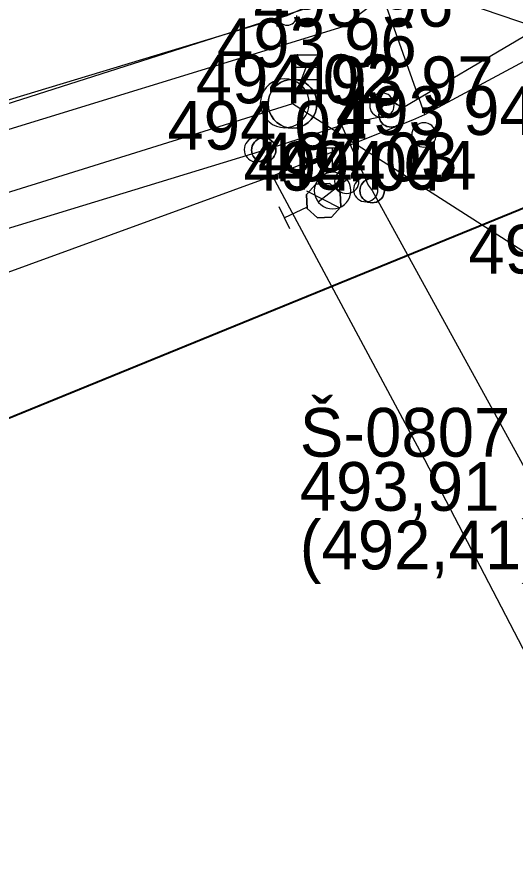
# Model space of a CAD drawing. Extents: x -695326 to -694942, y -1122979 to -1122738.
# Drawn here: x -695088.22 to -695078.02, y -1122949.89 to -1122932.52 of the extents above; entities that cross this region are included whole.
import ezdxf

# ---------------------------------------------------------------- set-up
doc = ezdxf.new("R2010")
doc.units = 0
for name, color, linetype in [('Level 26', 7, 'Continuous'), ('Level 29', 7, 'Continuous'), ('Level 30', 7, 'Continuous'), ('Level 31', 7, 'Continuous'), ('Level 35', 7, 'Continuous'), ('Level 36', 7, 'Continuous'), ('Level 38', 7, 'Continuous'), ('Level 42', 7, 'Continuous'), ('Level 44', 7, 'Continuous'), ('Level 48', 7, 'Continuous'), ('Level 51', 7, 'Continuous'), ('Level 53', 7, 'Continuous'), ('Rozhraní ploch', 7, 'Continuous')]:
    doc.layers.add(name, color=color, linetype=linetype)

msp = doc.modelspace()

# ---------------------------------------------------------------- linework, layer by layer
at = {"layer": 'Level 26'}
msp.add_lwpolyline([(-695082.89, -1122932.49), (-695082.887, -1122932.525), (-695082.878, -1122932.558), (-695082.863, -1122932.59), (-695082.843, -1122932.619), (-695082.819, -1122932.643), (-695082.79, -1122932.663), (-695082.758, -1122932.678), (-695082.725, -1122932.687), (-695082.69, -1122932.69), (-695082.655, -1122932.687), (-695082.622, -1122932.678), (-695082.59, -1122932.663), (-695082.561, -1122932.643), (-695082.537, -1122932.619), (-695082.517, -1122932.59), (-695082.502, -1122932.558), (-695082.493, -1122932.525), (-695082.49, -1122932.49)], dxfattribs=at)
at = {"layer": 'Level 29'}
for p, q in [((-695080.75, -1122934.33), (-695080.75, -1122934.33)), ((-695083.32, -1122935.24), (-695083.32, -1122935.24)), ((-695081.47, -1122935.89), (-695081.47, -1122935.89)), ((-695081.76, -1122936.08), (-695081.76, -1122936.08)), ((-695081.08, -1122936.06), (-695081.08, -1122936.06))]:
    msp.add_line(p, q, dxfattribs=at)
for points in [[(-695080.5, -1122934.33), (-695080.504, -1122934.287), (-695080.515, -1122934.244), (-695080.533, -1122934.205), (-695080.558, -1122934.169), (-695080.589, -1122934.138), (-695080.625, -1122934.113), (-695080.664, -1122934.095), (-695080.707, -1122934.084), (-695080.75, -1122934.08), (-695080.793, -1122934.084), (-695080.836, -1122934.095), (-695080.875, -1122934.113), (-695080.911, -1122934.138), (-695080.942, -1122934.169), (-695080.967, -1122934.205), (-695080.985, -1122934.244), (-695080.996, -1122934.287), (-695081, -1122934.33), (-695080.996, -1122934.373), (-695080.985, -1122934.416), (-695080.967, -1122934.455), (-695080.942, -1122934.491), (-695080.911, -1122934.522), (-695080.875, -1122934.547), (-695080.836, -1122934.565), (-695080.793, -1122934.576), (-695080.75, -1122934.58), (-695080.707, -1122934.576), (-695080.664, -1122934.565), (-695080.625, -1122934.547), (-695080.589, -1122934.522), (-695080.558, -1122934.491), (-695080.533, -1122934.455), (-695080.515, -1122934.416), (-695080.504, -1122934.373), (-695080.5, -1122934.33)], [(-695083.07, -1122935.24), (-695083.074, -1122935.197), (-695083.085, -1122935.154), (-695083.103, -1122935.115), (-695083.128, -1122935.079), (-695083.159, -1122935.048), (-695083.195, -1122935.023), (-695083.234, -1122935.005), (-695083.277, -1122934.994), (-695083.32, -1122934.99), (-695083.363, -1122934.994), (-695083.406, -1122935.005), (-695083.445, -1122935.023), (-695083.481, -1122935.048), (-695083.512, -1122935.079), (-695083.537, -1122935.115), (-695083.555, -1122935.154), (-695083.566, -1122935.197), (-695083.57, -1122935.24), (-695083.566, -1122935.283), (-695083.555, -1122935.326), (-695083.537, -1122935.365), (-695083.512, -1122935.401), (-695083.481, -1122935.432), (-695083.445, -1122935.457), (-695083.406, -1122935.475), (-695083.363, -1122935.486), (-695083.32, -1122935.49), (-695083.277, -1122935.486), (-695083.234, -1122935.475), (-695083.195, -1122935.457), (-695083.159, -1122935.432), (-695083.128, -1122935.401), (-695083.103, -1122935.365), (-695083.085, -1122935.326), (-695083.074, -1122935.283), (-695083.07, -1122935.24)], [(-695082.01, -1122935.205), (-695081.51, -1122935.205)], [(-695081.76, -1122935.705), (-695081.76, -1122935.205)], [(-695081.22, -1122935.89), (-695081.224, -1122935.847), (-695081.235, -1122935.804), (-695081.253, -1122935.765), (-695081.278, -1122935.729), (-695081.309, -1122935.698), (-695081.345, -1122935.673), (-695081.384, -1122935.655), (-695081.427, -1122935.644), (-695081.47, -1122935.64), (-695081.513, -1122935.644), (-695081.556, -1122935.655), (-695081.595, -1122935.673), (-695081.631, -1122935.698), (-695081.662, -1122935.729), (-695081.687, -1122935.765), (-695081.705, -1122935.804), (-695081.716, -1122935.847), (-695081.72, -1122935.89), (-695081.716, -1122935.933), (-695081.705, -1122935.976), (-695081.687, -1122936.015), (-695081.662, -1122936.051), (-695081.631, -1122936.082), (-695081.595, -1122936.107), (-695081.556, -1122936.125), (-695081.513, -1122936.136), (-695081.47, -1122936.14), (-695081.427, -1122936.136), (-695081.384, -1122936.125), (-695081.345, -1122936.107), (-695081.309, -1122936.082), (-695081.278, -1122936.051), (-695081.253, -1122936.015), (-695081.235, -1122935.976), (-695081.224, -1122935.933), (-695081.22, -1122935.89)], [(-695081.385, -1122936.08), (-695081.391, -1122936.015), (-695081.408, -1122935.952), (-695081.435, -1122935.892), (-695081.473, -1122935.839), (-695081.519, -1122935.793), (-695081.572, -1122935.755), (-695081.632, -1122935.728), (-695081.695, -1122935.711), (-695081.76, -1122935.705), (-695081.825, -1122935.711), (-695081.888, -1122935.728), (-695081.947, -1122935.755), (-695082.001, -1122935.793), (-695082.047, -1122935.839), (-695082.085, -1122935.892), (-695082.112, -1122935.952), (-695082.129, -1122936.015), (-695082.135, -1122936.08), (-695082.129, -1122936.145), (-695082.112, -1122936.208), (-695082.085, -1122936.267), (-695082.047, -1122936.321), (-695082.001, -1122936.367), (-695081.947, -1122936.405), (-695081.888, -1122936.432), (-695081.825, -1122936.449), (-695081.76, -1122936.455), (-695081.695, -1122936.449), (-695081.632, -1122936.432), (-695081.572, -1122936.405), (-695081.519, -1122936.367), (-695081.473, -1122936.321), (-695081.435, -1122936.267), (-695081.408, -1122936.208), (-695081.391, -1122936.145), (-695081.385, -1122936.08)], [(-695080.83, -1122936.06), (-695080.834, -1122936.017), (-695080.845, -1122935.974), (-695080.863, -1122935.935), (-695080.888, -1122935.899), (-695080.919, -1122935.868), (-695080.955, -1122935.843), (-695080.994, -1122935.825), (-695081.037, -1122935.814), (-695081.08, -1122935.81), (-695081.123, -1122935.814), (-695081.166, -1122935.825), (-695081.205, -1122935.843), (-695081.241, -1122935.868), (-695081.272, -1122935.899), (-695081.297, -1122935.935), (-695081.315, -1122935.974), (-695081.326, -1122936.017), (-695081.33, -1122936.06), (-695081.326, -1122936.103), (-695081.315, -1122936.146), (-695081.297, -1122936.185), (-695081.272, -1122936.221), (-695081.241, -1122936.252), (-695081.205, -1122936.277), (-695081.166, -1122936.295), (-695081.123, -1122936.306), (-695081.08, -1122936.31), (-695081.037, -1122936.306), (-695080.994, -1122936.295), (-695080.955, -1122936.277), (-695080.919, -1122936.252), (-695080.888, -1122936.221), (-695080.863, -1122936.185), (-695080.845, -1122936.146), (-695080.834, -1122936.103), (-695080.83, -1122936.06)], [(-695082.054, -1122936.311), (-695081.464, -1122935.848)]]:
    msp.add_lwpolyline(points, dxfattribs=at)
at = {"layer": 'Level 30'}
for p, q in [((-695082.3, -1122933.55), (-695082.3, -1122933.55)), ((-695082.74, -1122934.29), (-695082.74, -1122934.29))]:
    msp.add_line(p, q, dxfattribs=at)
for points in [[(-695082.55, -1122933.801), (-695082.05, -1122933.801), (-695082.05, -1122933.3), (-695082.55, -1122933.3), (-695082.55, -1122933.801)], [(-695082.55, -1122933.55), (-695082.05, -1122933.55)], [(-695082.24, -1122934.29), (-695082.248, -1122934.203), (-695082.27, -1122934.119), (-695082.307, -1122934.04), (-695082.357, -1122933.969), (-695082.419, -1122933.907), (-695082.49, -1122933.857), (-695082.569, -1122933.82), (-695082.653, -1122933.798), (-695082.74, -1122933.79), (-695082.827, -1122933.798), (-695082.911, -1122933.82), (-695082.99, -1122933.857), (-695083.061, -1122933.907), (-695083.123, -1122933.969), (-695083.173, -1122934.04), (-695083.21, -1122934.119), (-695083.232, -1122934.203), (-695083.24, -1122934.29), (-695083.232, -1122934.377), (-695083.21, -1122934.461), (-695083.173, -1122934.54), (-695083.123, -1122934.611), (-695083.061, -1122934.673), (-695082.99, -1122934.723), (-695082.911, -1122934.76), (-695082.827, -1122934.782), (-695082.74, -1122934.79), (-695082.653, -1122934.782), (-695082.569, -1122934.76), (-695082.49, -1122934.723), (-695082.419, -1122934.673), (-695082.357, -1122934.611), (-695082.307, -1122934.54), (-695082.27, -1122934.461), (-695082.248, -1122934.377), (-695082.24, -1122934.29)]]:
    msp.add_lwpolyline(points, dxfattribs=at)
at = {"layer": 'Level 31'}
msp.add_line((-695079.89, -1122934.94), (-695079.89, -1122934.94), dxfattribs=at)
msp.add_lwpolyline([(-695079.64, -1122934.94), (-695079.644, -1122934.897), (-695079.655, -1122934.854), (-695079.673, -1122934.815), (-695079.698, -1122934.779), (-695079.729, -1122934.748), (-695079.765, -1122934.723), (-695079.804, -1122934.705), (-695079.847, -1122934.694), (-695079.89, -1122934.69), (-695079.933, -1122934.694), (-695079.976, -1122934.705), (-695080.015, -1122934.723), (-695080.051, -1122934.748), (-695080.082, -1122934.779), (-695080.107, -1122934.815), (-695080.125, -1122934.854), (-695080.136, -1122934.897), (-695080.14, -1122934.94), (-695080.136, -1122934.983), (-695080.125, -1122935.026), (-695080.107, -1122935.065), (-695080.082, -1122935.101), (-695080.051, -1122935.132), (-695080.015, -1122935.157), (-695079.976, -1122935.175), (-695079.933, -1122935.186), (-695079.89, -1122935.19), (-695079.847, -1122935.186), (-695079.804, -1122935.175), (-695079.765, -1122935.157), (-695079.729, -1122935.132), (-695079.698, -1122935.101), (-695079.673, -1122935.065), (-695079.655, -1122935.026), (-695079.644, -1122934.983), (-695079.64, -1122934.94)], dxfattribs=at)
at = {"layer": 'Level 35'}
msp.add_line((-695082.58, -1122934.3), (-695082.3, -1122933.55), dxfattribs=at)
for points in [[(-695122.183, -1122978.845), (-695130.45, -1122957.93), (-695095.39, -1122943.61), (-695072.77, -1122934.37), (-695099.42, -1122862.69)], [(-695131.247, -1122978.864), (-695132.65, -1122975.94), (-695157.61, -1122969.63), (-695140.47, -1122958.8), (-695136.63, -1122948.53), (-695119.01, -1122943.49), (-695100.79, -1122937.97), (-695082.69, -1122932.49), (-695067.48, -1122925.68), (-695054.28, -1122919.15), (-695039.04, -1122911.54), (-695024.78, -1122904.45), (-695010.56, -1122897.35), (-694996.02, -1122890.13), (-694983.12, -1122883.66), (-694965.65, -1122874.99), (-694952.69, -1122868.61), (-694948.627, -1122866.586)]]:
    msp.add_lwpolyline(points, dxfattribs=at)
at = {"layer": 'Level 36'}
for p, q in [((-695076.08, -1122931.88), (-695080.56, -1122934.53)), ((-695080.56, -1122934.53), (-695081.58, -1122934.74)), ((-695082.99, -1122935.78), (-695080.12, -1122934.63))]:
    msp.add_line(p, q, dxfattribs=at)
for points in [[(-695080.12, -1122934.63), (-695079.87, -1122934.52), (-695067.92, -1122928.09), (-695061.28, -1122924.38), (-695055.24, -1122920.99), (-695043.92, -1122915.38), (-695041.46, -1122911.18), (-695031.8, -1122906.42), (-695019.5, -1122900.12), (-695018.26, -1122899.49), (-695013.65, -1122897.25), (-695010.42, -1122895.62), (-694999.32, -1122890.29), (-694992.82, -1122887.05), (-694976.036, -1122879.197)], [(-695080.48, -1122922.5), (-695080.09, -1122922.37), (-695078.02, -1122927.55), (-695078.08, -1122929.81), (-695080.4, -1122930.84), (-695080.06, -1122931.88), (-695072.77, -1122934.37)], [(-695079.87, -1122934.52), (-695081.2, -1122930.76), (-695081.62, -1122930.91)], [(-695083.17, -1122935.25), (-695081.781, -1122934.805), (-695081.58, -1122934.74)], [(-695081.58, -1122934.74), (-695081.03, -1122935.97), (-695080.95, -1122936.08)], [(-695134.34, -1122973.03), (-695133.962, -1122972.86), (-695138.962, -1122954.566), (-695138.77, -1122954.48), (-695126.25, -1122948.73), (-695098.58, -1122939.97), (-695083.17, -1122935.25)], [(-695134.55, -1122961.53), (-695132.51, -1122957.25), (-695132.03, -1122956.26), (-695129.88, -1122955.26), (-695122.6, -1122951.79), (-695118.68, -1122949.8), (-695111.26, -1122946.33), (-695098.73, -1122941.53), (-695092.08, -1122939.09), (-695082.99, -1122935.78)], [(-695060.508, -1122978.714), (-695066.08, -1122968.01), (-695069.94, -1122960.81), (-695074.02, -1122952.86), (-695079.87, -1122941.6), (-695082.99, -1122935.78)], [(-695080.95, -1122936.08), (-695066.03, -1122963.27), (-695064.437, -1122966.165)]]:
    msp.add_lwpolyline(points, dxfattribs=at)
at = {"layer": 'Level 38'}
msp.add_line((-695077.1, -1122937.81), (-695082.58, -1122934.3), dxfattribs=at)
msp.add_lwpolyline([(-695082.58, -1122934.3), (-695132.114, -1122949.771), (-695137.17, -1122949.78)], dxfattribs=at)
at = {"layer": 'Level 42'}
msp.add_line((-695072.77, -1122934.36), (-695130.4, -1122957.89), dxfattribs=at)
at = {"layer": 'Level 44'}
for p, q in [((-695082.58, -1122934.3), (-695082.58, -1122934.3)), ((-695080.56, -1122934.53), (-695080.56, -1122934.53)), ((-695083.17, -1122935.25), (-695083.17, -1122935.25)), ((-695081.62, -1122936.12), (-695081.62, -1122936.12)), ((-695080.95, -1122936.08), (-695080.95, -1122936.08))]:
    msp.add_line(p, q, dxfattribs=at)
for points in [[(-695082.08, -1122934.3), (-695082.088, -1122934.213), (-695082.11, -1122934.129), (-695082.147, -1122934.05), (-695082.197, -1122933.979), (-695082.259, -1122933.917), (-695082.33, -1122933.867), (-695082.409, -1122933.83), (-695082.493, -1122933.808), (-695082.58, -1122933.8), (-695082.667, -1122933.808), (-695082.751, -1122933.83), (-695082.83, -1122933.867), (-695082.901, -1122933.917), (-695082.963, -1122933.979), (-695083.013, -1122934.05), (-695083.05, -1122934.129), (-695083.072, -1122934.213), (-695083.08, -1122934.3), (-695083.072, -1122934.387), (-695083.05, -1122934.471), (-695083.013, -1122934.55), (-695082.963, -1122934.621), (-695082.901, -1122934.683), (-695082.83, -1122934.733), (-695082.751, -1122934.77), (-695082.667, -1122934.792), (-695082.58, -1122934.8), (-695082.493, -1122934.792), (-695082.409, -1122934.77), (-695082.33, -1122934.733), (-695082.259, -1122934.683), (-695082.197, -1122934.621), (-695082.147, -1122934.55), (-695082.11, -1122934.471), (-695082.088, -1122934.387), (-695082.08, -1122934.3)], [(-695080.31, -1122934.53), (-695080.314, -1122934.487), (-695080.325, -1122934.444), (-695080.343, -1122934.405), (-695080.368, -1122934.369), (-695080.399, -1122934.338), (-695080.435, -1122934.313), (-695080.474, -1122934.295), (-695080.517, -1122934.284), (-695080.56, -1122934.28), (-695080.603, -1122934.284), (-695080.646, -1122934.295), (-695080.685, -1122934.313), (-695080.721, -1122934.338), (-695080.752, -1122934.369), (-695080.777, -1122934.405), (-695080.795, -1122934.444), (-695080.806, -1122934.487), (-695080.81, -1122934.53), (-695080.806, -1122934.573), (-695080.795, -1122934.616), (-695080.777, -1122934.655), (-695080.752, -1122934.691), (-695080.721, -1122934.722), (-695080.685, -1122934.747), (-695080.646, -1122934.765), (-695080.603, -1122934.776), (-695080.56, -1122934.78), (-695080.517, -1122934.776), (-695080.474, -1122934.765), (-695080.435, -1122934.747), (-695080.399, -1122934.722), (-695080.368, -1122934.691), (-695080.343, -1122934.655), (-695080.325, -1122934.616), (-695080.314, -1122934.573), (-695080.31, -1122934.53)], [(-695082.92, -1122935.25), (-695082.924, -1122935.207), (-695082.935, -1122935.164), (-695082.953, -1122935.125), (-695082.978, -1122935.089), (-695083.009, -1122935.058), (-695083.045, -1122935.033), (-695083.084, -1122935.015), (-695083.127, -1122935.004), (-695083.17, -1122935), (-695083.213, -1122935.004), (-695083.256, -1122935.015), (-695083.295, -1122935.033), (-695083.331, -1122935.058), (-695083.362, -1122935.089), (-695083.387, -1122935.125), (-695083.405, -1122935.164), (-695083.416, -1122935.207), (-695083.42, -1122935.25), (-695083.416, -1122935.293), (-695083.405, -1122935.336), (-695083.387, -1122935.375), (-695083.362, -1122935.411), (-695083.331, -1122935.442), (-695083.295, -1122935.467), (-695083.256, -1122935.485), (-695083.213, -1122935.496), (-695083.17, -1122935.5), (-695083.127, -1122935.496), (-695083.084, -1122935.485), (-695083.045, -1122935.467), (-695083.009, -1122935.442), (-695082.978, -1122935.411), (-695082.953, -1122935.375), (-695082.935, -1122935.336), (-695082.924, -1122935.293), (-695082.92, -1122935.25)], [(-695080.7, -1122936.08), (-695080.704, -1122936.037), (-695080.715, -1122935.994), (-695080.733, -1122935.955), (-695080.758, -1122935.919), (-695080.789, -1122935.888), (-695080.825, -1122935.863), (-695080.864, -1122935.845), (-695080.907, -1122935.834), (-695080.95, -1122935.83), (-695080.993, -1122935.834), (-695081.036, -1122935.845), (-695081.075, -1122935.863), (-695081.111, -1122935.888), (-695081.142, -1122935.919), (-695081.167, -1122935.955), (-695081.185, -1122935.994), (-695081.196, -1122936.037), (-695081.2, -1122936.08), (-695081.196, -1122936.123), (-695081.185, -1122936.166), (-695081.167, -1122936.205), (-695081.142, -1122936.241), (-695081.111, -1122936.272), (-695081.075, -1122936.297), (-695081.036, -1122936.315), (-695080.993, -1122936.326), (-695080.95, -1122936.33), (-695080.907, -1122936.326), (-695080.864, -1122936.315), (-695080.825, -1122936.297), (-695080.789, -1122936.272), (-695080.758, -1122936.241), (-695080.733, -1122936.205), (-695080.715, -1122936.166), (-695080.704, -1122936.123), (-695080.7, -1122936.08)], [(-695082.103, -1122935.947), (-695082.296, -1122936.159), (-695082.282, -1122936.446), (-695082.07, -1122936.639), (-695081.783, -1122936.625), (-695081.59, -1122936.413), (-695081.604, -1122936.126), (-695081.816, -1122935.933), (-695082.103, -1122935.947)], [(-695081.619, -1122936.431), (-695082.29, -1122936.095)], [(-695082.638, -1122936.863), (-695082.852, -1122936.411)], [(-695082.293, -1122936.424), (-695082.745, -1122936.637)]]:
    msp.add_lwpolyline(points, dxfattribs=at)
for points in [[(-695082.493, -1122934.792), (-695082.58, -1122934.8), (-695082.667, -1122934.792), (-695082.751, -1122934.77), (-695082.83, -1122934.733), (-695082.901, -1122934.683), (-695082.963, -1122934.621), (-695083.013, -1122934.55), (-695083.05, -1122934.471), (-695083.072, -1122934.387), (-695083.08, -1122934.3), (-695083.072, -1122934.213), (-695083.05, -1122934.129), (-695083.013, -1122934.05), (-695082.963, -1122933.979), (-695082.901, -1122933.917), (-695082.83, -1122933.867), (-695082.751, -1122933.83), (-695082.667, -1122933.808), (-695082.58, -1122933.8), (-695082.493, -1122933.808), (-695082.409, -1122933.83), (-695082.33, -1122933.867), (-695082.259, -1122933.917), (-695082.197, -1122933.979), (-695082.147, -1122934.05), (-695082.11, -1122934.129), (-695082.088, -1122934.213), (-695082.08, -1122934.3), (-695082.088, -1122934.387), (-695082.11, -1122934.471), (-695082.147, -1122934.55), (-695082.197, -1122934.621), (-695082.259, -1122934.683), (-695082.33, -1122934.733), (-695082.409, -1122934.77)], [(-695080.517, -1122934.776), (-695080.56, -1122934.78), (-695080.603, -1122934.776), (-695080.646, -1122934.765), (-695080.685, -1122934.747), (-695080.721, -1122934.722), (-695080.752, -1122934.691), (-695080.777, -1122934.655), (-695080.795, -1122934.616), (-695080.806, -1122934.573), (-695080.81, -1122934.53), (-695080.806, -1122934.487), (-695080.795, -1122934.444), (-695080.777, -1122934.405), (-695080.752, -1122934.369), (-695080.721, -1122934.338), (-695080.685, -1122934.313), (-695080.646, -1122934.295), (-695080.603, -1122934.284), (-695080.56, -1122934.28), (-695080.517, -1122934.284), (-695080.474, -1122934.295), (-695080.435, -1122934.313), (-695080.399, -1122934.338), (-695080.368, -1122934.369), (-695080.343, -1122934.405), (-695080.325, -1122934.444), (-695080.314, -1122934.487), (-695080.31, -1122934.53), (-695080.314, -1122934.573), (-695080.325, -1122934.616), (-695080.343, -1122934.655), (-695080.368, -1122934.691), (-695080.399, -1122934.722), (-695080.435, -1122934.747), (-695080.474, -1122934.765)], [(-695083.127, -1122935.496), (-695083.17, -1122935.5), (-695083.213, -1122935.496), (-695083.256, -1122935.485), (-695083.295, -1122935.467), (-695083.331, -1122935.442), (-695083.362, -1122935.411), (-695083.387, -1122935.375), (-695083.405, -1122935.336), (-695083.416, -1122935.293), (-695083.42, -1122935.25), (-695083.416, -1122935.207), (-695083.405, -1122935.164), (-695083.387, -1122935.125), (-695083.362, -1122935.089), (-695083.331, -1122935.058), (-695083.295, -1122935.033), (-695083.256, -1122935.015), (-695083.213, -1122935.004), (-695083.17, -1122935), (-695083.127, -1122935.004), (-695083.084, -1122935.015), (-695083.045, -1122935.033), (-695083.009, -1122935.058), (-695082.978, -1122935.089), (-695082.953, -1122935.125), (-695082.935, -1122935.164), (-695082.924, -1122935.207), (-695082.92, -1122935.25), (-695082.924, -1122935.293), (-695082.935, -1122935.336), (-695082.953, -1122935.375), (-695082.978, -1122935.411), (-695083.009, -1122935.442), (-695083.045, -1122935.467), (-695083.084, -1122935.485)], [(-695080.907, -1122936.326), (-695080.95, -1122936.33), (-695080.993, -1122936.326), (-695081.036, -1122936.315), (-695081.075, -1122936.297), (-695081.111, -1122936.272), (-695081.142, -1122936.241), (-695081.167, -1122936.205), (-695081.185, -1122936.166), (-695081.196, -1122936.123), (-695081.2, -1122936.08), (-695081.196, -1122936.037), (-695081.185, -1122935.994), (-695081.167, -1122935.955), (-695081.142, -1122935.919), (-695081.111, -1122935.888), (-695081.075, -1122935.863), (-695081.036, -1122935.845), (-695080.993, -1122935.834), (-695080.95, -1122935.83), (-695080.907, -1122935.834), (-695080.864, -1122935.845), (-695080.825, -1122935.863), (-695080.789, -1122935.888), (-695080.758, -1122935.919), (-695080.733, -1122935.955), (-695080.715, -1122935.994), (-695080.704, -1122936.037), (-695080.7, -1122936.08), (-695080.704, -1122936.123), (-695080.715, -1122936.166), (-695080.733, -1122936.205), (-695080.758, -1122936.241), (-695080.789, -1122936.272), (-695080.825, -1122936.297), (-695080.864, -1122936.315)], [(-695081.783, -1122936.625), (-695082.07, -1122936.639), (-695082.282, -1122936.446), (-695082.296, -1122936.159), (-695082.103, -1122935.947), (-695081.816, -1122935.933), (-695081.604, -1122936.126), (-695081.59, -1122936.413)]]:
    msp.add_lwpolyline(points, close=True, dxfattribs=at)
at = {"layer": 'Level 51'}
for p, q in [((-695081.55, -1122932.72), (-695081.55, -1122932.72)), ((-695082.3, -1122933.55), (-695082.3, -1122933.55)), ((-695082.74, -1122934.29), (-695082.74, -1122934.29)), ((-695080.75, -1122934.33), (-695080.75, -1122934.33)), ((-695079.89, -1122934.94), (-695079.89, -1122934.94)), ((-695083.32, -1122935.24), (-695083.32, -1122935.24)), ((-695081.47, -1122935.89), (-695081.47, -1122935.89)), ((-695081.76, -1122936.08), (-695081.76, -1122936.08)), ((-695081.08, -1122936.06), (-695081.08, -1122936.06))]:
    msp.add_line(p, q, dxfattribs=at)
at = {"layer": 'Level 53'}
msp.add_line((-695080.16, -1122931.66), (-695117.44, -1122943.58), dxfattribs=at)
at = {"layer": 'Rozhraní ploch'}
msp.add_lwpolyline([(-695078.88, -1122927.75), (-695078.67, -1122928.75), (-695079.45, -1122931.14), (-695081.55, -1122932.72), (-695097.9, -1122937.75), (-695120.76, -1122944.73), (-695134.78, -1122948.87), (-695138.25, -1122948.9), (-695141.57, -1122948.15), (-695143.91, -1122946.04)], dxfattribs=at)

# ---------------------------------------------------------------- texts
at = {"layer": 'Level 48'}
for s, p in [('Š-0807', (-695082.432, -1122941.536)), ('493,91', (-695082.432, -1122942.646)), ('(492,41)', (-695082.432, -1122943.846))]:
    msp.add_text(s, height=1, dxfattribs=at).set_placement(p)
at = {"layer": 'Level 53'}
for s, p in [('493 96', (-695083.377, -1122932.72)), ('493 96', (-695084.127, -1122933.55)), ('494 02', (-695084.563, -1122934.29)), ('493 97', (-695082.55, -1122934.33)), ('493 94', (-695081.69, -1122934.94)), ('494 04', (-695085.143, -1122935.24)), ('494 03', (-695083.293, -1122935.89)), ('494 04', (-695083.583, -1122936.08)), ('494 04', (-695082.903, -1122936.06)), ('493 95', (-695078.98, -1122937.78))]:
    msp.add_text(s, height=1, dxfattribs=at).set_placement(p)

doc.saveas('drawing.dxf')
